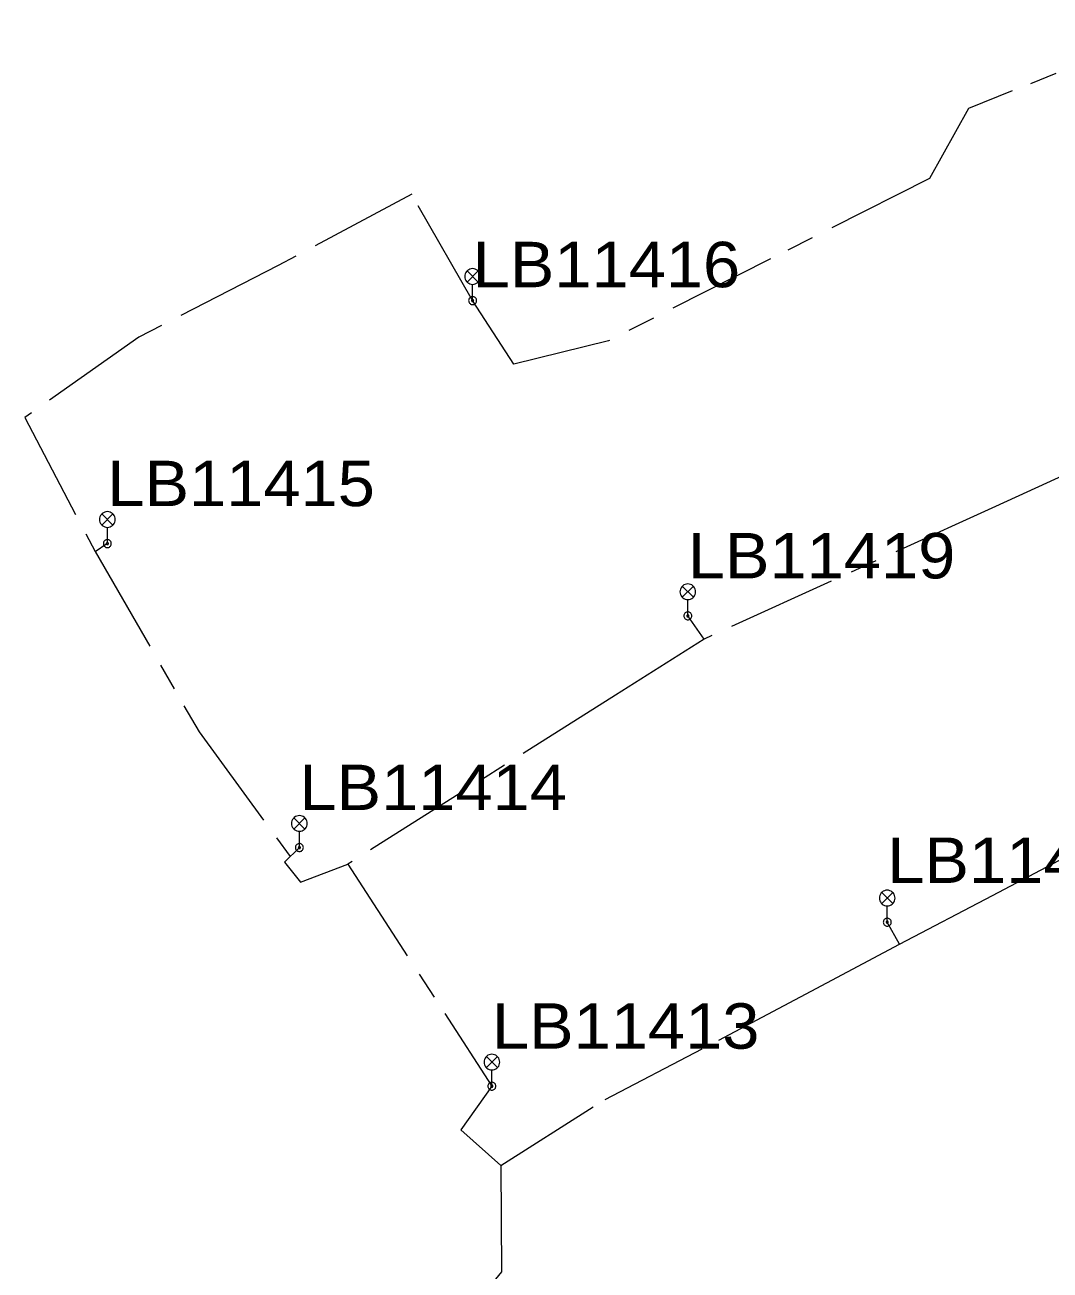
# Model space of a CAD drawing. Extents: x -688049 to -687261, y -973611 to -973038.
# Drawn here: x -687864.7 to -687815.7, y -973374.1 to -973314.6 of the extents above; entities that cross this region are included whole.
import ezdxf

# ---------------------------------------------------------------- set-up
doc = ezdxf.new("R2010")
doc.units = 0
doc.header["$LTSCALE"] = 0.87
doc.linetypes.add('LONG_DASH_SHORT_DASH', pattern=[9.9, 6, -1.2, 1.5, -1.2])
doc.layers.add('1', color=7, linetype='Continuous', lineweight=13)

msp = doc.modelspace()

# ---------------------------------------------------------------- linework, layer by layer
at = {"layer": '1', "linetype": 'LONG_DASH_SHORT_DASH'}
for p, q in [((-687809.65, -973314.61), (-687817.544, -973317.763)), ((-687861.32, -973339.75), (-687860.76, -973339.37)), ((-687832.25, -973343.93), (-687836.478, -973346.599)), ((-687836.478, -973346.599), (-687849.26, -973354.67)), ((-687822.92, -973358.49), (-687818.494, -973356.165)), ((-687844.632, -973361.8), (-687842.38, -973365.27))]:
    msp.add_line(p, q, dxfattribs=at)
at = {"layer": '1'}
for p, q in [((-687843.565, -973326.355), (-687843.035, -973326.885)), ((-687843.565, -973326.885), (-687843.035, -973326.355)), ((-687843.3, -973327.77), (-687843.3, -973326.995)), ((-687861, -973337.955), (-687860.47, -973338.485)), ((-687861, -973338.485), (-687860.47, -973337.955)), ((-687860.735, -973339.37), (-687860.735, -973338.595)), ((-687833.295, -973341.405), (-687832.765, -973341.935)), ((-687833.295, -973341.935), (-687832.765, -973341.405)), ((-687833.03, -973342.82), (-687833.03, -973342.045)), ((-687851.835, -973352.465), (-687851.305, -973352.995)), ((-687851.835, -973352.995), (-687851.305, -973352.465)), ((-687851.57, -973353.88), (-687851.57, -973353.105)), ((-687823.775, -973356.025), (-687823.245, -973356.555)), ((-687823.775, -973356.555), (-687823.245, -973356.025)), ((-687823.51, -973357.44), (-687823.51, -973356.665)), ((-687842.645, -973363.855), (-687842.115, -973364.385)), ((-687842.645, -973364.385), (-687842.115, -973363.855)), ((-687842.38, -973365.27), (-687842.38, -973364.495))]:
    msp.add_line(p, q, dxfattribs=at)
at = {"layer": '1', "linetype": 'LONG_DASH_SHORT_DASH'}
for points in [[(-687817.544, -973317.763), (-687819.64, -973318.6), (-687821.5, -973321.94), (-687829.084, -973325.779)], [(-687843.3, -973327.77), (-687846.21, -973322.69), (-687852.58, -973326.1), (-687859.24, -973329.51), (-687864.67, -973333.35), (-687861.32, -973339.75), (-687857.077, -973347.115)], [(-687829.084, -973325.779), (-687836.81, -973329.69), (-687841.34, -973330.8), (-687843.3, -973327.77)], [(-687814.33, -973333.54), (-687813.8, -973335.52), (-687818.35, -973337.594)], [(-687818.35, -973337.594), (-687832.25, -973343.93), (-687833.03, -973342.82)], [(-687857.077, -973347.115), (-687856.36, -973348.36), (-687852.014, -973354.314)], [(-687818.494, -973356.165), (-687815.02, -973354.34), (-687807.46, -973351.33), (-687808.19, -973349.79)], [(-687851.57, -973353.88), (-687852.283, -973354.577), (-687851.52, -973355.53), (-687849.26, -973354.67), (-687844.632, -973361.8)], [(-687827.136, -973360.732), (-687822.92, -973358.49), (-687823.51, -973357.44)], [(-687841.96, -973369.05), (-687836.97, -973365.9), (-687831.55, -973363.08), (-687827.136, -973360.732)], [(-687842.38, -973365.27), (-687843.86, -973367.35), (-687841.96, -973369.05), (-687841.93, -973374.14), (-687846.1, -973379.17)]]:
    msp.add_lwpolyline(points, dxfattribs=at)
at = {"layer": '1'}
for points in [[(-687842.925, -973326.62), (-687842.931, -973326.555), (-687842.948, -973326.492), (-687842.975, -973326.432), (-687843.013, -973326.379), (-687843.059, -973326.333), (-687843.112, -973326.295), (-687843.172, -973326.268), (-687843.235, -973326.251), (-687843.3, -973326.245), (-687843.365, -973326.251), (-687843.428, -973326.268), (-687843.488, -973326.295), (-687843.541, -973326.333), (-687843.587, -973326.379), (-687843.625, -973326.432), (-687843.652, -973326.492), (-687843.669, -973326.555), (-687843.675, -973326.62), (-687843.669, -973326.685), (-687843.652, -973326.748), (-687843.625, -973326.808), (-687843.587, -973326.861), (-687843.541, -973326.907), (-687843.488, -973326.945), (-687843.428, -973326.972), (-687843.365, -973326.989), (-687843.3, -973326.995), (-687843.235, -973326.989), (-687843.172, -973326.972), (-687843.112, -973326.945), (-687843.059, -973326.907), (-687843.013, -973326.861), (-687842.975, -973326.808), (-687842.948, -973326.748), (-687842.931, -973326.685)], [(-687843.11, -973327.77), (-687843.113, -973327.737), (-687843.121, -973327.705), (-687843.135, -973327.675), (-687843.154, -973327.648), (-687843.178, -973327.624), (-687843.205, -973327.605), (-687843.235, -973327.591), (-687843.267, -973327.583), (-687843.3, -973327.58), (-687843.333, -973327.583), (-687843.365, -973327.591), (-687843.395, -973327.605), (-687843.422, -973327.624), (-687843.446, -973327.648), (-687843.465, -973327.675), (-687843.479, -973327.705), (-687843.487, -973327.737), (-687843.49, -973327.77), (-687843.487, -973327.803), (-687843.479, -973327.835), (-687843.465, -973327.865), (-687843.446, -973327.892), (-687843.422, -973327.916), (-687843.395, -973327.935), (-687843.365, -973327.949), (-687843.333, -973327.957), (-687843.3, -973327.96), (-687843.267, -973327.957), (-687843.235, -973327.949), (-687843.205, -973327.935), (-687843.178, -973327.916), (-687843.154, -973327.892), (-687843.135, -973327.865), (-687843.121, -973327.835), (-687843.113, -973327.803)], [(-687843.25, -973327.77), (-687843.251, -973327.761), (-687843.253, -973327.753), (-687843.257, -973327.745), (-687843.262, -973327.738), (-687843.268, -973327.732), (-687843.275, -973327.727), (-687843.283, -973327.723), (-687843.291, -973327.721), (-687843.3, -973327.72), (-687843.309, -973327.721), (-687843.317, -973327.723), (-687843.325, -973327.727), (-687843.332, -973327.732), (-687843.338, -973327.738), (-687843.343, -973327.745), (-687843.347, -973327.753), (-687843.349, -973327.761), (-687843.35, -973327.77), (-687843.349, -973327.779), (-687843.347, -973327.787), (-687843.343, -973327.795), (-687843.338, -973327.802), (-687843.332, -973327.808), (-687843.325, -973327.813), (-687843.317, -973327.817), (-687843.309, -973327.819), (-687843.3, -973327.82), (-687843.291, -973327.819), (-687843.283, -973327.817), (-687843.275, -973327.813), (-687843.268, -973327.808), (-687843.262, -973327.802), (-687843.257, -973327.795), (-687843.253, -973327.787), (-687843.251, -973327.779)], [(-687860.36, -973338.22), (-687860.366, -973338.155), (-687860.383, -973338.092), (-687860.41, -973338.033), (-687860.448, -973337.979), (-687860.494, -973337.933), (-687860.548, -973337.895), (-687860.607, -973337.868), (-687860.67, -973337.851), (-687860.735, -973337.845), (-687860.8, -973337.851), (-687860.863, -973337.868), (-687860.922, -973337.895), (-687860.976, -973337.933), (-687861.022, -973337.979), (-687861.06, -973338.033), (-687861.087, -973338.092), (-687861.104, -973338.155), (-687861.11, -973338.22), (-687861.104, -973338.285), (-687861.087, -973338.348), (-687861.06, -973338.408), (-687861.022, -973338.461), (-687860.976, -973338.507), (-687860.922, -973338.545), (-687860.863, -973338.572), (-687860.8, -973338.589), (-687860.735, -973338.595), (-687860.67, -973338.589), (-687860.607, -973338.572), (-687860.548, -973338.545), (-687860.494, -973338.507), (-687860.448, -973338.461), (-687860.41, -973338.408), (-687860.383, -973338.348), (-687860.366, -973338.285)], [(-687860.545, -973339.37), (-687860.548, -973339.337), (-687860.556, -973339.305), (-687860.57, -973339.275), (-687860.589, -973339.248), (-687860.613, -973339.224), (-687860.64, -973339.205), (-687860.67, -973339.191), (-687860.702, -973339.183), (-687860.735, -973339.18), (-687860.768, -973339.183), (-687860.8, -973339.191), (-687860.83, -973339.205), (-687860.857, -973339.224), (-687860.881, -973339.248), (-687860.9, -973339.275), (-687860.914, -973339.305), (-687860.922, -973339.337), (-687860.925, -973339.37), (-687860.922, -973339.403), (-687860.914, -973339.435), (-687860.9, -973339.465), (-687860.881, -973339.492), (-687860.857, -973339.516), (-687860.83, -973339.535), (-687860.8, -973339.549), (-687860.768, -973339.557), (-687860.735, -973339.56), (-687860.702, -973339.557), (-687860.67, -973339.549), (-687860.64, -973339.535), (-687860.613, -973339.516), (-687860.589, -973339.492), (-687860.57, -973339.465), (-687860.556, -973339.435), (-687860.548, -973339.403)], [(-687860.685, -973339.37), (-687860.686, -973339.361), (-687860.688, -973339.353), (-687860.692, -973339.345), (-687860.697, -973339.338), (-687860.703, -973339.332), (-687860.71, -973339.327), (-687860.718, -973339.323), (-687860.726, -973339.321), (-687860.735, -973339.32), (-687860.744, -973339.321), (-687860.752, -973339.323), (-687860.76, -973339.327), (-687860.767, -973339.332), (-687860.773, -973339.338), (-687860.778, -973339.345), (-687860.782, -973339.353), (-687860.784, -973339.361), (-687860.785, -973339.37), (-687860.784, -973339.379), (-687860.782, -973339.387), (-687860.778, -973339.395), (-687860.773, -973339.402), (-687860.767, -973339.408), (-687860.76, -973339.413), (-687860.752, -973339.417), (-687860.744, -973339.419), (-687860.735, -973339.42), (-687860.726, -973339.419), (-687860.718, -973339.417), (-687860.71, -973339.413), (-687860.703, -973339.408), (-687860.697, -973339.402), (-687860.692, -973339.395), (-687860.688, -973339.387), (-687860.686, -973339.379)], [(-687832.655, -973341.67), (-687832.661, -973341.605), (-687832.678, -973341.542), (-687832.705, -973341.482), (-687832.743, -973341.429), (-687832.789, -973341.383), (-687832.842, -973341.345), (-687832.902, -973341.318), (-687832.965, -973341.301), (-687833.03, -973341.295), (-687833.095, -973341.301), (-687833.158, -973341.318), (-687833.218, -973341.345), (-687833.271, -973341.383), (-687833.317, -973341.429), (-687833.355, -973341.482), (-687833.382, -973341.542), (-687833.399, -973341.605), (-687833.405, -973341.67), (-687833.399, -973341.735), (-687833.382, -973341.798), (-687833.355, -973341.857), (-687833.317, -973341.911), (-687833.271, -973341.957), (-687833.218, -973341.995), (-687833.158, -973342.022), (-687833.095, -973342.039), (-687833.03, -973342.045), (-687832.965, -973342.039), (-687832.902, -973342.022), (-687832.842, -973341.995), (-687832.789, -973341.957), (-687832.743, -973341.911), (-687832.705, -973341.857), (-687832.678, -973341.798), (-687832.661, -973341.735)], [(-687832.84, -973342.82), (-687832.843, -973342.787), (-687832.851, -973342.755), (-687832.865, -973342.725), (-687832.884, -973342.698), (-687832.908, -973342.674), (-687832.935, -973342.655), (-687832.965, -973342.641), (-687832.997, -973342.633), (-687833.03, -973342.63), (-687833.063, -973342.633), (-687833.095, -973342.641), (-687833.125, -973342.655), (-687833.152, -973342.674), (-687833.176, -973342.698), (-687833.195, -973342.725), (-687833.209, -973342.755), (-687833.217, -973342.787), (-687833.22, -973342.82), (-687833.217, -973342.853), (-687833.209, -973342.885), (-687833.195, -973342.915), (-687833.176, -973342.942), (-687833.152, -973342.966), (-687833.125, -973342.985), (-687833.095, -973342.999), (-687833.063, -973343.007), (-687833.03, -973343.01), (-687832.997, -973343.007), (-687832.965, -973342.999), (-687832.935, -973342.985), (-687832.908, -973342.966), (-687832.884, -973342.942), (-687832.865, -973342.915), (-687832.851, -973342.885), (-687832.843, -973342.853)], [(-687832.98, -973342.82), (-687832.981, -973342.811), (-687832.983, -973342.803), (-687832.987, -973342.795), (-687832.992, -973342.788), (-687832.998, -973342.782), (-687833.005, -973342.777), (-687833.013, -973342.773), (-687833.021, -973342.771), (-687833.03, -973342.77), (-687833.039, -973342.771), (-687833.047, -973342.773), (-687833.055, -973342.777), (-687833.062, -973342.782), (-687833.068, -973342.788), (-687833.073, -973342.795), (-687833.077, -973342.803), (-687833.079, -973342.811), (-687833.08, -973342.82), (-687833.079, -973342.829), (-687833.077, -973342.837), (-687833.073, -973342.845), (-687833.068, -973342.852), (-687833.062, -973342.858), (-687833.055, -973342.863), (-687833.047, -973342.867), (-687833.039, -973342.869), (-687833.03, -973342.87), (-687833.021, -973342.869), (-687833.013, -973342.867), (-687833.005, -973342.863), (-687832.998, -973342.858), (-687832.992, -973342.852), (-687832.987, -973342.845), (-687832.983, -973342.837), (-687832.981, -973342.829)], [(-687851.195, -973352.73), (-687851.201, -973352.665), (-687851.218, -973352.602), (-687851.245, -973352.543), (-687851.283, -973352.489), (-687851.329, -973352.443), (-687851.383, -973352.405), (-687851.442, -973352.378), (-687851.505, -973352.361), (-687851.57, -973352.355), (-687851.635, -973352.361), (-687851.698, -973352.378), (-687851.758, -973352.405), (-687851.811, -973352.443), (-687851.857, -973352.489), (-687851.895, -973352.543), (-687851.922, -973352.602), (-687851.939, -973352.665), (-687851.945, -973352.73), (-687851.939, -973352.795), (-687851.922, -973352.858), (-687851.895, -973352.918), (-687851.857, -973352.971), (-687851.811, -973353.017), (-687851.758, -973353.055), (-687851.698, -973353.082), (-687851.635, -973353.099), (-687851.57, -973353.105), (-687851.505, -973353.099), (-687851.442, -973353.082), (-687851.383, -973353.055), (-687851.329, -973353.017), (-687851.283, -973352.971), (-687851.245, -973352.918), (-687851.218, -973352.858), (-687851.201, -973352.795)], [(-687851.38, -973353.88), (-687851.383, -973353.847), (-687851.391, -973353.815), (-687851.405, -973353.785), (-687851.424, -973353.758), (-687851.448, -973353.734), (-687851.475, -973353.715), (-687851.505, -973353.701), (-687851.537, -973353.693), (-687851.57, -973353.69), (-687851.603, -973353.693), (-687851.635, -973353.701), (-687851.665, -973353.715), (-687851.692, -973353.734), (-687851.716, -973353.758), (-687851.735, -973353.785), (-687851.749, -973353.815), (-687851.757, -973353.847), (-687851.76, -973353.88), (-687851.757, -973353.913), (-687851.749, -973353.945), (-687851.735, -973353.975), (-687851.716, -973354.002), (-687851.692, -973354.026), (-687851.665, -973354.045), (-687851.635, -973354.059), (-687851.603, -973354.067), (-687851.57, -973354.07), (-687851.537, -973354.067), (-687851.505, -973354.059), (-687851.475, -973354.045), (-687851.448, -973354.026), (-687851.424, -973354.002), (-687851.405, -973353.975), (-687851.391, -973353.945), (-687851.383, -973353.913)], [(-687851.52, -973353.88), (-687851.521, -973353.871), (-687851.523, -973353.863), (-687851.527, -973353.855), (-687851.532, -973353.848), (-687851.538, -973353.842), (-687851.545, -973353.837), (-687851.553, -973353.833), (-687851.561, -973353.831), (-687851.57, -973353.83), (-687851.579, -973353.831), (-687851.587, -973353.833), (-687851.595, -973353.837), (-687851.602, -973353.842), (-687851.608, -973353.848), (-687851.613, -973353.855), (-687851.617, -973353.863), (-687851.619, -973353.871), (-687851.62, -973353.88), (-687851.619, -973353.889), (-687851.617, -973353.897), (-687851.613, -973353.905), (-687851.608, -973353.912), (-687851.602, -973353.918), (-687851.595, -973353.923), (-687851.587, -973353.927), (-687851.579, -973353.929), (-687851.57, -973353.93), (-687851.561, -973353.929), (-687851.553, -973353.927), (-687851.545, -973353.923), (-687851.538, -973353.918), (-687851.532, -973353.912), (-687851.527, -973353.905), (-687851.523, -973353.897), (-687851.521, -973353.889)], [(-687823.135, -973356.29), (-687823.141, -973356.225), (-687823.158, -973356.162), (-687823.185, -973356.102), (-687823.223, -973356.049), (-687823.269, -973356.003), (-687823.322, -973355.965), (-687823.382, -973355.938), (-687823.445, -973355.921), (-687823.51, -973355.915), (-687823.575, -973355.921), (-687823.638, -973355.938), (-687823.698, -973355.965), (-687823.751, -973356.003), (-687823.797, -973356.049), (-687823.835, -973356.102), (-687823.862, -973356.162), (-687823.879, -973356.225), (-687823.885, -973356.29), (-687823.879, -973356.355), (-687823.862, -973356.418), (-687823.835, -973356.477), (-687823.797, -973356.531), (-687823.751, -973356.577), (-687823.698, -973356.615), (-687823.638, -973356.642), (-687823.575, -973356.659), (-687823.51, -973356.665), (-687823.445, -973356.659), (-687823.382, -973356.642), (-687823.322, -973356.615), (-687823.269, -973356.577), (-687823.223, -973356.531), (-687823.185, -973356.477), (-687823.158, -973356.418), (-687823.141, -973356.355)], [(-687823.32, -973357.44), (-687823.323, -973357.407), (-687823.331, -973357.375), (-687823.345, -973357.345), (-687823.364, -973357.318), (-687823.388, -973357.294), (-687823.415, -973357.275), (-687823.445, -973357.261), (-687823.477, -973357.253), (-687823.51, -973357.25), (-687823.543, -973357.253), (-687823.575, -973357.261), (-687823.605, -973357.275), (-687823.632, -973357.294), (-687823.656, -973357.318), (-687823.675, -973357.345), (-687823.689, -973357.375), (-687823.697, -973357.407), (-687823.7, -973357.44), (-687823.697, -973357.473), (-687823.689, -973357.505), (-687823.675, -973357.535), (-687823.656, -973357.562), (-687823.632, -973357.586), (-687823.605, -973357.605), (-687823.575, -973357.619), (-687823.543, -973357.627), (-687823.51, -973357.63), (-687823.477, -973357.627), (-687823.445, -973357.619), (-687823.415, -973357.605), (-687823.388, -973357.586), (-687823.364, -973357.562), (-687823.345, -973357.535), (-687823.331, -973357.505), (-687823.323, -973357.473)], [(-687823.46, -973357.44), (-687823.461, -973357.431), (-687823.463, -973357.423), (-687823.467, -973357.415), (-687823.472, -973357.408), (-687823.478, -973357.402), (-687823.485, -973357.397), (-687823.493, -973357.393), (-687823.501, -973357.391), (-687823.51, -973357.39), (-687823.519, -973357.391), (-687823.527, -973357.393), (-687823.535, -973357.397), (-687823.542, -973357.402), (-687823.548, -973357.408), (-687823.553, -973357.415), (-687823.557, -973357.423), (-687823.559, -973357.431), (-687823.56, -973357.44), (-687823.559, -973357.449), (-687823.557, -973357.457), (-687823.553, -973357.465), (-687823.548, -973357.472), (-687823.542, -973357.478), (-687823.535, -973357.483), (-687823.527, -973357.487), (-687823.519, -973357.489), (-687823.51, -973357.49), (-687823.501, -973357.489), (-687823.493, -973357.487), (-687823.485, -973357.483), (-687823.478, -973357.478), (-687823.472, -973357.472), (-687823.467, -973357.465), (-687823.463, -973357.457), (-687823.461, -973357.449)], [(-687842.005, -973364.12), (-687842.011, -973364.055), (-687842.028, -973363.992), (-687842.055, -973363.932), (-687842.093, -973363.879), (-687842.139, -973363.833), (-687842.192, -973363.795), (-687842.252, -973363.768), (-687842.315, -973363.751), (-687842.38, -973363.745), (-687842.445, -973363.751), (-687842.508, -973363.768), (-687842.568, -973363.795), (-687842.621, -973363.833), (-687842.667, -973363.879), (-687842.705, -973363.932), (-687842.732, -973363.992), (-687842.749, -973364.055), (-687842.755, -973364.12), (-687842.749, -973364.185), (-687842.732, -973364.248), (-687842.705, -973364.308), (-687842.667, -973364.361), (-687842.621, -973364.407), (-687842.568, -973364.445), (-687842.508, -973364.472), (-687842.445, -973364.489), (-687842.38, -973364.495), (-687842.315, -973364.489), (-687842.252, -973364.472), (-687842.192, -973364.445), (-687842.139, -973364.407), (-687842.093, -973364.361), (-687842.055, -973364.308), (-687842.028, -973364.248), (-687842.011, -973364.185)], [(-687842.19, -973365.27), (-687842.193, -973365.237), (-687842.201, -973365.205), (-687842.215, -973365.175), (-687842.234, -973365.148), (-687842.258, -973365.124), (-687842.285, -973365.105), (-687842.315, -973365.091), (-687842.347, -973365.083), (-687842.38, -973365.08), (-687842.413, -973365.083), (-687842.445, -973365.091), (-687842.475, -973365.105), (-687842.502, -973365.124), (-687842.526, -973365.148), (-687842.545, -973365.175), (-687842.559, -973365.205), (-687842.567, -973365.237), (-687842.57, -973365.27), (-687842.567, -973365.303), (-687842.559, -973365.335), (-687842.545, -973365.365), (-687842.526, -973365.392), (-687842.502, -973365.416), (-687842.475, -973365.435), (-687842.445, -973365.449), (-687842.413, -973365.457), (-687842.38, -973365.46), (-687842.347, -973365.457), (-687842.315, -973365.449), (-687842.285, -973365.435), (-687842.258, -973365.416), (-687842.234, -973365.392), (-687842.215, -973365.365), (-687842.201, -973365.335), (-687842.193, -973365.303)], [(-687842.33, -973365.27), (-687842.331, -973365.261), (-687842.333, -973365.253), (-687842.337, -973365.245), (-687842.342, -973365.238), (-687842.348, -973365.232), (-687842.355, -973365.227), (-687842.363, -973365.223), (-687842.371, -973365.221), (-687842.38, -973365.22), (-687842.389, -973365.221), (-687842.397, -973365.223), (-687842.405, -973365.227), (-687842.412, -973365.232), (-687842.418, -973365.238), (-687842.423, -973365.245), (-687842.427, -973365.253), (-687842.429, -973365.261), (-687842.43, -973365.27), (-687842.429, -973365.279), (-687842.427, -973365.287), (-687842.423, -973365.295), (-687842.418, -973365.302), (-687842.412, -973365.308), (-687842.405, -973365.313), (-687842.397, -973365.317), (-687842.389, -973365.319), (-687842.38, -973365.32), (-687842.371, -973365.319), (-687842.363, -973365.317), (-687842.355, -973365.313), (-687842.348, -973365.308), (-687842.342, -973365.302), (-687842.337, -973365.295), (-687842.333, -973365.287), (-687842.331, -973365.279)]]:
    msp.add_lwpolyline(points, close=True, dxfattribs=at)

# ---------------------------------------------------------------- texts
at = {"layer": '1', "width": 1.1}
for s, p in [('LB11416', (-687843.3, -973327.132)), ('LB11415', (-687860.735, -973337.582)), ('LB11419', (-687833.03, -973341.032)), ('LB11414', (-687851.57, -973352.092)), ('LB11407', (-687823.51, -973355.568)), ('LB11413', (-687842.38, -973363.482))]:
    msp.add_text(s, height=2.168, dxfattribs=at).set_placement(p)

doc.saveas('drawing.dxf')
